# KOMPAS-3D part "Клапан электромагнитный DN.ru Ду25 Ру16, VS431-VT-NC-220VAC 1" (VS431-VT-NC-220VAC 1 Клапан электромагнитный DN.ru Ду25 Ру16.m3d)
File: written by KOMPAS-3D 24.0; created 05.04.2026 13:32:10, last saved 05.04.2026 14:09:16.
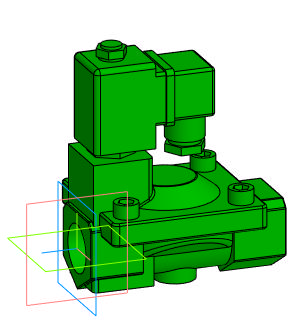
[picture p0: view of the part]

Document properties: Автор: artio; Полное имя файла: C:\Users\artio\OneDrive\Рабочий стол\Клапан электромагнитный DN.ru\VS431\VS431-VT-NC\VS431-VT-NC-220VAC\Ду25\VS431-VT-NC-220VAC 1 Клапан электромагнитный DN.ru Ду25 Ру16.m3d

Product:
- Body: Тело 1  | qty 1
    Масса: 1.729172
- Part/product: Клапан электромагнитный DN.ru Ду25 Ру16  | designation VS431-VT-NC-220VAC 1
    Масса: 1.267
    Раздел спецификации: Прочие изделия
    Примечание: D130-04714
    additional columns: ef56311e-7521-43dc-8291-0e6108b3d81d; artio; c; Шероховатость не задана; Да

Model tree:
1. Операция без истории:1

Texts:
  VS431-VT-NC-220VAC 1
